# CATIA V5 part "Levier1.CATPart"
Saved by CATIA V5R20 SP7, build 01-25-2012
Part number: Levier1
Bounding box of the stored display mesh (mm): x 0 to 15, y -6 to 82, z 144.044 to 159.956
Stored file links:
  J:\ACHTUNG2\Levier1.CATPart
  J:\ACHTUNG2\cmilovidof.CATProduct
  J:\ACHTUNG\IAO non optimisé fini et qui marche à rendre\Levier1.CATPart
  J:\ACHTUNG2\skl_Levier1.CATPart
  J:\ACHTUNG\IAO non optimisé fini et qui marche à rendre\Bielle5.CATPart
  J:\ACHTUNG\IAO non optimisé fini et qui marche à rendre\Bielle4.CATPart
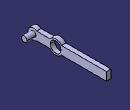
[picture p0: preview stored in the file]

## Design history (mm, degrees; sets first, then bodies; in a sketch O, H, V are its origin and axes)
Parameters
  LENGTH = 64 mm
  LENGTH = 4 mm {= LENGTH  *4mm/64mm}
  LENGTH = 4 mm {= LENGTH *4mm/64mm}
  LENGTH = 4 mm {= LENGTH *4mm/64mm}
External parameters (linked from other documents)
  External.diam_roue = 64 mm
Set1
  Plane1: linked copy from another document
  Line1 "Axe_LevierBielles": linked copy from another document
  Line2 "Axe_LevierBati": linked copy from another document
  Line3 "7-13": linked copy from another document
  Point1: linked copy from another document
  Plane2: linked copy from another document
  Line4 "Axe_Bielle5Levier1": linked copy from another document
Body1 (main body)
  Sketch1 on Plane1, origin (0, 0, 0), H (0, 1, 0), V (0, 0, 1)
    construction circle A1 centre (0, 152) radius 6
    point P1 (3.7482, 156.6852)
    construction circle A2 centre (25, 152) radius 8
    point P2 (18.5155, 156.6852)
    construction line L1 (3.7482, 156.6852) -> (18.5155, 156.6852)
    line L2 (18.5155, 156.6852) -> (3.7482, 156.6852)
    construction line L3 (18.5155, 156.6852) -> (25.8907, 156.6852)
    point P3 (18.0718, 156)
    line L4 (31.4845, 156.6852) -> (82, 156.6852)
    line L5 (82, 156.6852) -> (82, 147.3148)
    line L6 (82, 147.3148) -> (31.4845, 147.3148)
    construction line L7 (31.4845, 147.3148) -> (18.5155, 147.3148)
    line L8 (18.5155, 147.3148) -> (3.7482, 147.3148)
    arc A3 centre (25, 152) radius 8 from (31.4845, 156.6852) to (18.5155, 156.6852) ccw
    arc A4 centre (25, 152) radius 8 from (18.5155, 147.3148) to (31.4845, 147.3148) ccw
    arc A5 centre (0, 152) radius 6 from (3.7482, 156.6852) to (3.7482, 147.3148) ccw
    point P5 (31.4845, 147.3148)
    point P6 (31.4845, 147.3148)
    reference projected line E1 (0, 152) -> (82, 152) from Line3
    reference projected line E2 (0, 152) -> (82, 152) from Line3
    reference projected point E3 (82, 152) from Point1
    circle A6 centre (25, 152) radius 6
    point P14 (28.7482, 156.6852)
    reference projected point E4 (25, 152) from Line2
    reference projected point E5 (0, 152) from Line1
    radius A3 = 8 {= External.diam_roue *8mm/64mm}
    radius A4 = 8 {= External.diam_roue *8mm/64mm}
    radius A5 = 6 {= External.diam_roue *6mm/64mm}
    radius A6 = 6 {= External.diam_roue *6/64}
    coincidence: P1 A1, P2 A2, P3 A2, P6 P5, L5 E3, A6 P14, P14 L3
    horizontal: L1 H, L2 H, L3 H, L4 H, L6 H, L7 H, L8 H
    vertical: L5 V
    symmetry: L8 L2 E1, L6 L4 E2
    concentricity: A2 E4, A1 E5
  Pad1: profile Sketch1, direction (1, 0, 0), length 5
  Sketch2 on end face of Pad1, origin (5, 0, 0), H (0, 1, 0), V (0, 0, 1)
    circle A1 centre (0, 152) radius 3
    reference projected point E1 (0, 152) from Line1
    radius A1 = 3 {= 3*External.diam_roue /64}
    concentricity: A1 E1
  Pad2: profile Sketch2, direction (1, 0, 0), length 10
